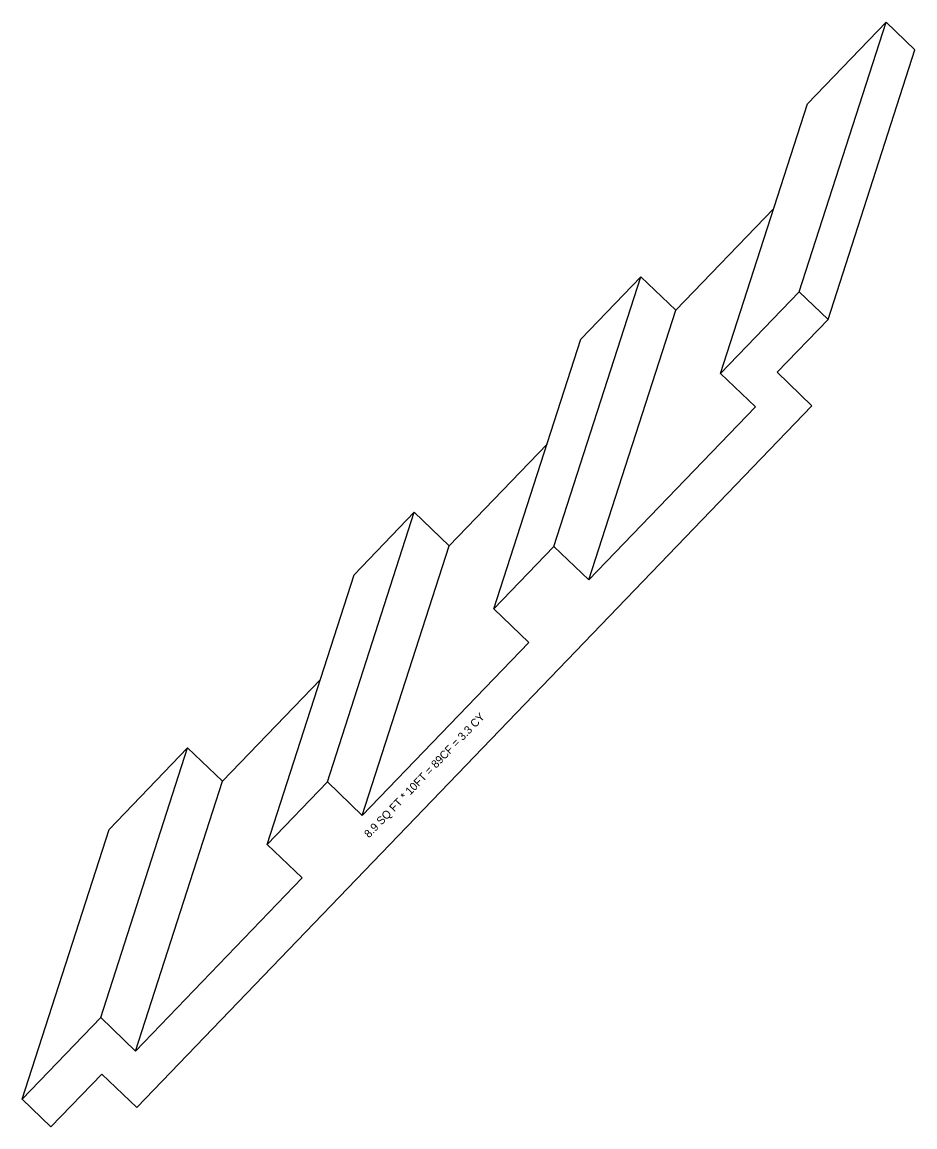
# Model space of a CAD drawing. Extents: x 2252703 to 2264864, y 13787568 to 13790989.
# Drawn here: x 2252907.51 to 2252918.66, y 13788623.02 to 13788636.83 of the extents above; entities that cross this region are included whole.
import ezdxf

# ---------------------------------------------------------------- set-up
doc = ezdxf.new("R2010")
doc.units = 0
doc.layers.add('D_DRN_INLET', color=7, linetype='Continuous')

msp = doc.modelspace()

# ---------------------------------------------------------------- linework, layer by layer
at = {"layer": 'D_DRN_INLET'}
for p, q in [((2252917.214, 13788633.457), (2252918.299, 13788636.826)), ((2252918.299, 13788636.826), (2252917.317, 13788635.805)), ((2252918.66, 13788636.48), (2252918.299, 13788636.826)), ((2252917.575, 13788633.11), (2252918.66, 13788636.48)), ((2252916.232, 13788632.436), (2252917.317, 13788635.805)), ((2252915.673, 13788633.225), (2252916.895, 13788634.495)), ((2252914.152, 13788630.274), (2252915.238, 13788633.643)), ((2252914.487, 13788632.863), (2252915.238, 13788633.643)), ((2252915.238, 13788633.643), (2252915.673, 13788633.225)), ((2252917.214, 13788633.457), (2252916.232, 13788632.436)), ((2252917.575, 13788633.11), (2252917.214, 13788633.457)), ((2252914.588, 13788629.855), (2252915.673, 13788633.225)), ((2252917.575, 13788633.11), (2252916.939, 13788632.45)), ((2252913.401, 13788629.493), (2252914.487, 13788632.863)), ((2252916.232, 13788632.436), (2252916.667, 13788632.017)), ((2252916.939, 13788632.45), (2252917.374, 13788632.031)), ((2252908.94, 13788623.262), (2252917.374, 13788632.031)), ((2252914.588, 13788629.855), (2252916.667, 13788632.017)), ((2252912.842, 13788630.282), (2252914.065, 13788631.552)), ((2252911.322, 13788627.331), (2252912.407, 13788630.701)), ((2252911.656, 13788629.92), (2252912.407, 13788630.701)), ((2252912.407, 13788630.701), (2252912.842, 13788630.282)), ((2252911.757, 13788626.912), (2252912.842, 13788630.282)), ((2252913.401, 13788629.493), (2252914.152, 13788630.274)), ((2252914.152, 13788630.274), (2252914.588, 13788629.855)), ((2252910.57, 13788626.55), (2252911.656, 13788629.92)), ((2252913.837, 13788629.074), (2252913.401, 13788629.493)), ((2252911.757, 13788626.912), (2252913.837, 13788629.074)), ((2252910.011, 13788627.339), (2252911.234, 13788628.61)), ((2252908.491, 13788624.388), (2252909.576, 13788627.758)), ((2252908.594, 13788626.737), (2252909.576, 13788627.758)), ((2252909.576, 13788627.758), (2252910.011, 13788627.339)), ((2252908.926, 13788623.969), (2252910.011, 13788627.339)), ((2252910.57, 13788626.55), (2252911.322, 13788627.331)), ((2252911.322, 13788627.331), (2252911.757, 13788626.912)), ((2252907.509, 13788623.367), (2252908.594, 13788626.737)), ((2252911.006, 13788626.131), (2252910.57, 13788626.55)), ((2252908.926, 13788623.969), (2252911.006, 13788626.131)), ((2252907.509, 13788623.367), (2252908.491, 13788624.388)), ((2252908.491, 13788624.388), (2252908.926, 13788623.969)), ((2252907.869, 13788623.021), (2252908.504, 13788623.681)), ((2252908.504, 13788623.681), (2252908.94, 13788623.262)), ((2252907.509, 13788623.367), (2252907.869, 13788623.021))]:
    msp.add_line(p, q, dxfattribs=at)

# ---------------------------------------------------------------- texts
msp.add_text('8.9 SQ FT * 10FT = 89CF = 3.3 CY ', height=0.1, rotation=46.1117, dxfattribs=at).set_placement((2252911.842, 13788626.625))

doc.saveas('drawing.dxf')
